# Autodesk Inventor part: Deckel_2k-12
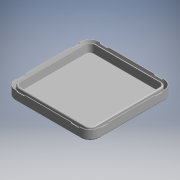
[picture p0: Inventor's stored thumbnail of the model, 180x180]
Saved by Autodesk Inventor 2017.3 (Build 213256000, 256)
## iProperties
Part Number: Deckel_2k-12
Material: Generic
Catalog Web Link: www.cadenas.de
Description: Deckel_2k-12-Deckel_2k-12
Vendor: SPELSBERG
Document SubType Name: Modeling
Designer: partserver
Manufacturer: SPELSBERG
Mass: 17.899 g
Surface Area: 236.655 cm^2
Volume: 17.899 cm^3
Density: 1 g/cm^3
Appearance: PSOLRGB-215-215-215
Category: PARTsolutions
Company: SPELSBERG
Title: Deckel_2k-12
Author: Cadenas PARTsolutions
Comments: Deckel_2k-12
PSOL_IDENT_0: {$CADENAS_DATA\23d-libs\spelsberg\pool\verbindungsdosen\parts\deckel_2k_12.prj},170 {VTYP=3D},{NB=De
PSOL_IDENT_1: ckel_2k-12},{LINA=Deckel_2k-12},{NN=Deckel_2k-12},{DATE=27.03.2020 09:10:35},{GEOMDATE=09.09.2014 10
PSOL_IDENT_2: :10:00},{VERSION=},{LINEID=10},{WBVAR=},{WBNUMERIC=}  {NB=Deckel_2k-12},{LINA=Deckel_2k-12},{KT=DUMM
PSOL_IDENT_3: Y},{CNSORDERNO=Deckel_2k-12}
NB: Deckel_2k-12
NN: Deckel_2k-12
NT: Deckel_2k-12
NBSYN: $CNSORDERNO.
LINA: Deckel_2k-12
CATALOG: Spelsberg
CNSORDERNO: Deckel_2k-12
SUPPLIER: SPELSBERG
ARTICLENO: Deckel_2k-12
BOMINFO: Deckel_2k-12
CREATOR: CADENAS GmbH
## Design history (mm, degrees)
sketch "Sketch_1"
  geometry: L1 (41, 9.5)-(-41, 9.5); L2 (-42.5, 8)-(-42.5, 0); L3 (-42.5, 0)-(-41.915, 0); L4 (-41.915, 0)-(-40.5, 5); L5 (-40.5, 5)-(-40.646, 7.784); L6 (-40.346, 8.1)-(-39.3, 8.1); L7 (-39, 7.8)-(-39, 1.1); L8 (-38, 0.1)-(-37.5, 0.1); L9 (-37.5, 0.1)-(-36.967, 7.721); L10 (-36.668, 8)-(36.668, 8); L11 (36.967, 7.721)-(37.5, 0.1); L12 (37.5, 0.1)-(38, 0.1); L13 (39, 1.1)-(39, 7.8); L14 (39.3, 8.1)-(40.346, 8.1); L15 (40.646, 7.784)-(40.5, 5); L16 (40.5, 5)-(41.915, 0); L17 (41.915, 0)-(42.5, 0); L18 (42.5, 0)-(42.5, 8); A1 r 1.5 centre (-41, 8) between (-41, 9.5) and (-42.5, 8); A2 r 0.3 centre (-40.346, 7.8) between (-40.346, 8.1) and (-40.646, 7.784); A3 r 0.3 centre (-39.3, 7.8) between (-39, 7.8) and (-39.3, 8.1); A4 r 1 centre (-38, 1.1) between (-39, 1.1) and (-38, 0.1); A5 r 0.3 centre (-36.668, 7.7) between (-36.668, 8) and (-36.967, 7.721); A6 r 0.3 centre (36.668, 7.7) between (36.967, 7.721) and (36.668, 8); A7 r 1 centre (38, 1.1) between (38, 0.1) and (39, 1.1); A8 r 0.3 centre (39.3, 7.8) between (39.3, 8.1) and (39, 7.8); A9 r 0.3 centre (40.346, 7.8) between (40.646, 7.784) and (40.346, 8.1); A10 r 1.5 centre (41, 8) between (42.5, 8) and (41, 9.5)
  constraints: 36 end point, 20 point on circle, 10 centre point
extrude "Extrusion1" join sketch "Sketch_1" stored distance "d0" = 66; taper "d1" = 0 deg
sketch "Sketch_2"
  geometry: L1 (42.5, 0)-(42.5, 8); L2 (41, 9.5)-(33, 9.5); L3 (33, 9.5)-(33, 8); L4 (33, 8)-(36.668, 8); L5 (36.967, 7.721)-(37.5, 0.1); L6 (37.5, 0.1)-(38, 0.1); L7 (39, 1.1)-(39, 7.8); L8 (39.3, 8.1)-(40.346, 8.1); L9 (40.646, 7.784)-(40.5, 5); L10 (40.5, 5)-(41.915, 0); L11 (41.915, 0)-(42.5, 0); A1 r 1.5 centre (41, 8) between (42.5, 8) and (41, 9.5); A2 r 0.3 centre (36.668, 7.7) between (36.967, 7.721) and (36.668, 8); A3 r 1 centre (38, 1.1) between (38, 0.1) and (39, 1.1); A4 r 0.3 centre (39.3, 7.8) between (39.3, 8.1) and (39, 7.8); A5 r 0.3 centre (40.346, 7.8) between (40.646, 7.784) and (40.346, 8.1)
  constraints: 22 end point, 10 point on circle, 5 centre point
extrude "Extrusion2" join sketch "Sketch_2" stored distance "d2" = 66; taper "d3" = 0 deg
sketch "Sketch_3"
  geometry: L1 (-33, 8)-(-33, 9.5); L2 (-33, 9.5)-(-41, 9.5); L3 (-42.5, 8)-(-42.5, 0); L4 (-42.5, 0)-(-41.915, 0); L5 (-41.915, 0)-(-40.5, 5); L6 (-40.5, 5)-(-40.646, 7.784); L7 (-40.346, 8.1)-(-39.3, 8.1); L8 (-39, 7.8)-(-39, 1.1); L9 (-38, 0.1)-(-37.5, 0.1); L10 (-37.5, 0.1)-(-36.967, 7.721); L11 (-36.668, 8)-(-33, 8); A1 r 1.5 centre (-41, 8) between (-41, 9.5) and (-42.5, 8); A2 r 0.3 centre (-40.346, 7.8) between (-40.346, 8.1) and (-40.646, 7.784); A3 r 0.3 centre (-39.3, 7.8) between (-39, 7.8) and (-39.3, 8.1); A4 r 1 centre (-38, 1.1) between (-39, 1.1) and (-38, 0.1); A5 r 0.3 centre (-36.668, 7.7) between (-36.668, 8) and (-36.967, 7.721)
  constraints: 22 end point, 10 point on circle, 5 centre point
extrude "Extrusion3" join sketch "Sketch_3" stored distance "d4" = 66; taper "d5" = 0 deg
sketch "Sketch_4"
  geometry: L1 (0, 33)-(-9.5, 33); L2 (-9.5, 33)-(-9.5, 41); L3 (-8, 42.5)-(0, 42.5); L4 (0, 42.5)-(0, 41.915); L5 (0, 41.915)-(-5, 40.5); L6 (-5, 40.5)-(-7.784, 40.646); L7 (-8.1, 40.346)-(-8.1, 39.3); L8 (-7.8, 39)-(-1.1, 39); L9 (-0.1, 38)-(-0.1, 37.5); L10 (-0.1, 37.5)-(-7.721, 36.967); L11 (-8, 36.668)-(-8, 33); L12 (-8, 33)-(-9.5, 33); A1 r 1.5 centre (-8, 41) between (-8, 42.5) and (-9.5, 41); A2 r 0.3 centre (-7.8, 40.346) between (-7.784, 40.646) and (-8.1, 40.346); A3 r 0.3 centre (-7.8, 39.3) between (-8.1, 39.3) and (-7.8, 39); A4 r 1 centre (-1.1, 38) between (-0.1, 38) and (-1.1, 39); A5 r 0.3 centre (-7.7, 36.668) between (-7.721, 36.967) and (-8, 36.668)
  constraints: 24 end point, 10 point on circle, 5 centre point
revolve "Revolution1" sketch "Sketch_4" stored, may be unused: angle "d6" = 90 deg
sketch "Sketch_5"
  geometry: L1 (-9.5, -33)-(0, -33); L2 (-8, -33)-(-8, -36.668); L3 (-7.721, -36.967)-(-0.1, -37.5); L4 (-0.1, -37.5)-(-0.1, -38); L5 (-1.1, -39)-(-7.8, -39); L6 (-8.1, -39.3)-(-8.1, -40.346); L7 (-7.784, -40.646)-(-5, -40.5); L8 (-5, -40.5)-(0, -41.915); L9 (0, -41.915)-(0, -42.5); L10 (0, -42.5)-(-8, -42.5); L11 (-9.5, -41)-(-9.5, -33); L12 (-9.5, -33)-(-8, -33); A1 r 0.3 centre (-7.7, -36.668) between (-8, -36.668) and (-7.721, -36.967); A2 r 1 centre (-1.1, -38) between (-1.1, -39) and (-0.1, -38); A3 r 0.3 centre (-7.8, -39.3) between (-7.8, -39) and (-8.1, -39.3); A4 r 0.3 centre (-7.8, -40.346) between (-8.1, -40.346) and (-7.784, -40.646); A5 r 1.5 centre (-8, -41) between (-9.5, -41) and (-8, -42.5)
  constraints: 24 end point, 10 point on circle, 5 centre point
revolve "Revolution2" sketch "Sketch_5" stored, may be unused: angle "d7" = 90 deg
sketch "Sketch_6"
  geometry: L1 (0, 33)-(-9.5, 33); L2 (-9.5, 33)-(-9.5, 41); L3 (-8, 42.5)-(0, 42.5); L4 (0, 42.5)-(0, 41.915); L5 (0, 41.915)-(-5, 40.5); L6 (-5, 40.5)-(-7.784, 40.646); L7 (-8.1, 40.346)-(-8.1, 39.3); L8 (-7.8, 39)-(-1.1, 39); L9 (-0.1, 38)-(-0.1, 37.5); L10 (-0.1, 37.5)-(-7.721, 36.967); L11 (-8, 36.668)-(-8, 33); L12 (-8, 33)-(-9.5, 33); A1 r 1.5 centre (-8, 41) between (-8, 42.5) and (-9.5, 41); A2 r 0.3 centre (-7.8, 40.346) between (-7.784, 40.646) and (-8.1, 40.346); A3 r 0.3 centre (-7.8, 39.3) between (-8.1, 39.3) and (-7.8, 39); A4 r 1 centre (-1.1, 38) between (-0.1, 38) and (-1.1, 39); A5 r 0.3 centre (-7.7, 36.668) between (-7.721, 36.967) and (-8, 36.668)
  constraints: 24 end point, 10 point on circle, 5 centre point
revolve "Revolution3" sketch "Sketch_6" stored, may be unused: angle "d8" = 90 deg
sketch "Sketch_7"
  geometry: L1 (-9.5, -33)-(0, -33); L2 (-8, -33)-(-8, -36.668); L3 (-7.721, -36.967)-(-0.1, -37.5); L4 (-0.1, -37.5)-(-0.1, -38); L5 (-1.1, -39)-(-7.8, -39); L6 (-8.1, -39.3)-(-8.1, -40.346); L7 (-7.784, -40.646)-(-5, -40.5); L8 (-5, -40.5)-(0, -41.915); L9 (0, -41.915)-(0, -42.5); L10 (0, -42.5)-(-8, -42.5); L11 (-9.5, -41)-(-9.5, -33); L12 (-9.5, -33)-(-8, -33); A1 r 0.3 centre (-7.7, -36.668) between (-8, -36.668) and (-7.721, -36.967); A2 r 1 centre (-1.1, -38) between (-1.1, -39) and (-0.1, -38); A3 r 0.3 centre (-7.8, -39.3) between (-7.8, -39) and (-8.1, -39.3); A4 r 0.3 centre (-7.8, -40.346) between (-8.1, -40.346) and (-7.784, -40.646); A5 r 1.5 centre (-8, -41) between (-9.5, -41) and (-8, -42.5)
  constraints: 24 end point, 10 point on circle, 5 centre point
revolve "Revolution4" sketch "Sketch_7" stored, may be unused: angle "d9" = 90 deg
sketch "Sketch_8"
  geometry: L1 (-25.213, -42.213)-(25.213, -42.213); L2 (25.213, -42.213)-(4, -21); L3 (4, -21)-(4, 42.5); L4 (4, 42.5)-(-4, 42.5); L5 (-4, 42.5)-(-4, -21); L6 (-4, -21)-(-25.213, -42.213)
  constraints: 12 end point
extrude "Extrusion4" cut sketch "Sketch_8" distance "d10" = 0.4; taper "d11" = 0 deg
sketch "Sketch_9"
  geometry: L1 (-36.5, 35.5)-(-36.5, 19.2); L2 (-35.5, 18.2)-(-13.2, 18.2); L3 (-12.2, 19.2)-(-12.2, 35.5); L4 (-13.2, 36.5)-(-35.5, 36.5); A1 r 1 centre (-35.5, 19.2) between (-36.5, 19.2) and (-35.5, 18.2); A2 r 1 centre (-13.2, 19.2) between (-13.2, 18.2) and (-12.2, 19.2); A3 r 1 centre (-13.2, 35.5) between (-12.2, 35.5) and (-13.2, 36.5); A4 r 1 centre (-35.5, 35.5) between (-35.5, 36.5) and (-36.5, 35.5)
  constraints: 8 end point, 8 point on circle, 4 centre point
extrude "Extrusion5" cut sketch "Sketch_9" distance "d12" = 0.3; taper "d13" = 0 deg
sketch "Sketch_10"
  geometry: L1 (-1, -31)-(0, -32); L2 (0, -32)-(3, -32); L3 (3, -32)-(3, 32); L4 (3, 32)-(0, 32); L5 (0, 32)-(-1, 31); L6 (-1, 31)-(-1, 24); L7 (-1, 24)-(0, 23); L8 (0, 23)-(2, 23); L9 (2, 23)-(2, -23); L10 (2, -23)-(0, -23); L11 (0, -23)-(-1, -24); L12 (-1, -24)-(-1, -31)
  constraints: 24 end point
extrude "Extrusion6" cut sketch "Sketch_10" distance "d14" = 1; taper "d15" = 0 deg
sketch "Sketch_11"
  geometry: L1 (-1, -31)-(0, -32); L2 (0, -32)-(3, -32); L3 (3, -32)-(3, 32); L4 (3, 32)-(0, 32); L5 (0, 32)-(-1, 31); L6 (-1, 31)-(-1, 24); L7 (-1, 24)-(0, 23); L8 (0, 23)-(2, 23); L9 (2, 23)-(2, -23); L10 (2, -23)-(0, -23); L11 (0, -23)-(-1, -24); L12 (-1, -24)-(-1, -31)
  constraints: 24 end point
extrude "Extrusion7" cut sketch "Sketch_11" distance "d16" = 1; taper "d17" = 0 deg
sketch "Sketch_12"
  geometry: L1 (-32, 3)-(-32, 0); L2 (-32, 0)-(-31, -1); L3 (-31, -1)-(-24, -1); L4 (-24, -1)-(-23, 0); L5 (-23, 0)-(-23, 2); L6 (-23, 2)-(23, 2); L7 (23, 2)-(23, 0); L8 (23, 0)-(24, -1); L9 (24, -1)-(31, -1); L10 (31, -1)-(32, 0); L11 (32, 0)-(32, 3); L12 (32, 3)-(-32, 3)
  constraints: 24 end point
extrude "Extrusion8" cut sketch "Sketch_12" distance "d18" = 1; taper "d19" = 0 deg
sketch "Sketch_13"
  geometry: L1 (-32, 3)-(-32, 0); L2 (-32, 0)-(-31, -1); L3 (-31, -1)-(-24, -1); L4 (-24, -1)-(-23, 0); L5 (-23, 0)-(-23, 2); L6 (-23, 2)-(23, 2); L7 (23, 2)-(23, 0); L8 (23, 0)-(24, -1); L9 (24, -1)-(31, -1); L10 (31, -1)-(32, 0); L11 (32, 0)-(32, 3); L12 (32, 3)-(-32, 3)
  constraints: 24 end point
extrude "Extrusion9" cut sketch "Sketch_13" distance "d20" = 1; taper "d21" = 0 deg
node "DECKEL_XY"
node "DECKEL_YZ"
node "DECKEL_ZX"
node "DECKEL_X"
node "DECKEL_Y"
node "DECKEL_Z"
node "DECKEL_Center"
body "Solid1"
